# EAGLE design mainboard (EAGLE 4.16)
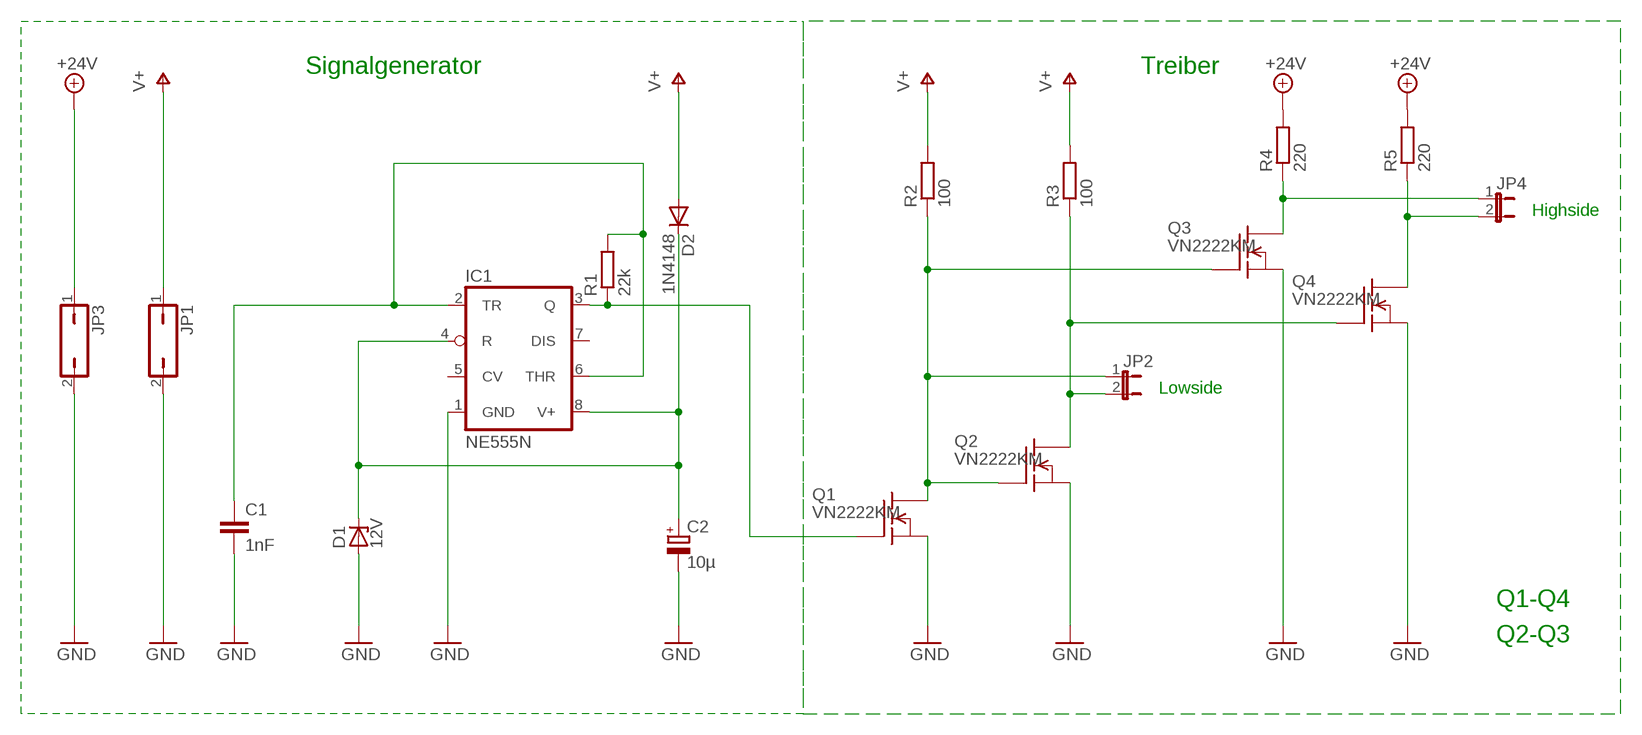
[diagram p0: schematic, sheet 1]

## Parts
C1  1nF  C-EU050-030X075  [C050-030X075]
C2  10µ  CPOL-EUE5-6  [E5-6]
D1  12V  ZENER-DIODEZD-10  [ZDIO-10]
D2  1N4148  [DO35-10]
IC1  NE555N  [DIL08]
JP1  JP1Q  [JP1]
JP2  JP1E  [JP1]
JP3  JP1Q  [JP1]
JP4  JP1E  [JP1]
Q1  VN2222KM  [TO237]
Q2  VN2222KM  [TO237]
Q3  VN2222KM  [TO237]
Q4  VN2222KM  [TO237]
R1  22k  R-EU_0207/10  [0207/10]
R2  100  R-EU_0207/10  [0207/10]
R3  100  R-EU_0207/10  [0207/10]
R4  220  R-EU_0207/10  [0207/10]
R5  220  R-EU_0207/10  [0207/10]

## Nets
+24V: JP3.1 R4.2 R5.2
GND: C1.2 C2.- D1.A IC1.1(GND) JP1.2 JP3.2 Q1.3(S) Q2.3(S) Q3.3(S) Q4.3(S)
N$1: C1.1 IC1.2(TR) IC1.6(THR) R1.2
N$2: IC1.3(Q) Q1.2(G) R1.1
N$3: C2.+ D1.C D2.C IC1.4(R) IC1.8(V+)
N$4: JP2.1 Q1.1(D) Q2.2(G) Q3.2(G) R2.1
N$5: JP2.2 Q2.1(D) Q4.2(G) R3.1
N$6: JP4.1 Q3.1(D) R4.1
N$7: JP4.2 Q4.1(D) R5.1
V+: D2.A JP1.1 R2.2 R3.2
Unconnected: IC1.5(CV) IC1.7(DIS)

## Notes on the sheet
- Signalgenerator | Treiber
- Highside
- Lowside
- Q1-Q4
- Q2-Q3

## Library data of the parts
C1 = rcl:C-EU: CAPACITOR, European symbol
C2 = rcl:CPOL-EU: POLARIZED CAPACITOR, European symbol
D1 = diode:ZENER-DIODE: Z-Diode
D2 = diode:1N4148: DIODE
IC1 = linear:*555: TIMER
JP1 JP3 = jumper:JP1Q: JUMPER
JP2 JP4 = jumper:JP1E: JUMPER
Q1-Q4 = transistor-fet:VN2222KM: N-Channel Enhancement MOSFET (VMOS); 60V; 0,5A; 7,5Ohm
R1-R5 = rcl:R-EU_: RESISTOR, European symbol

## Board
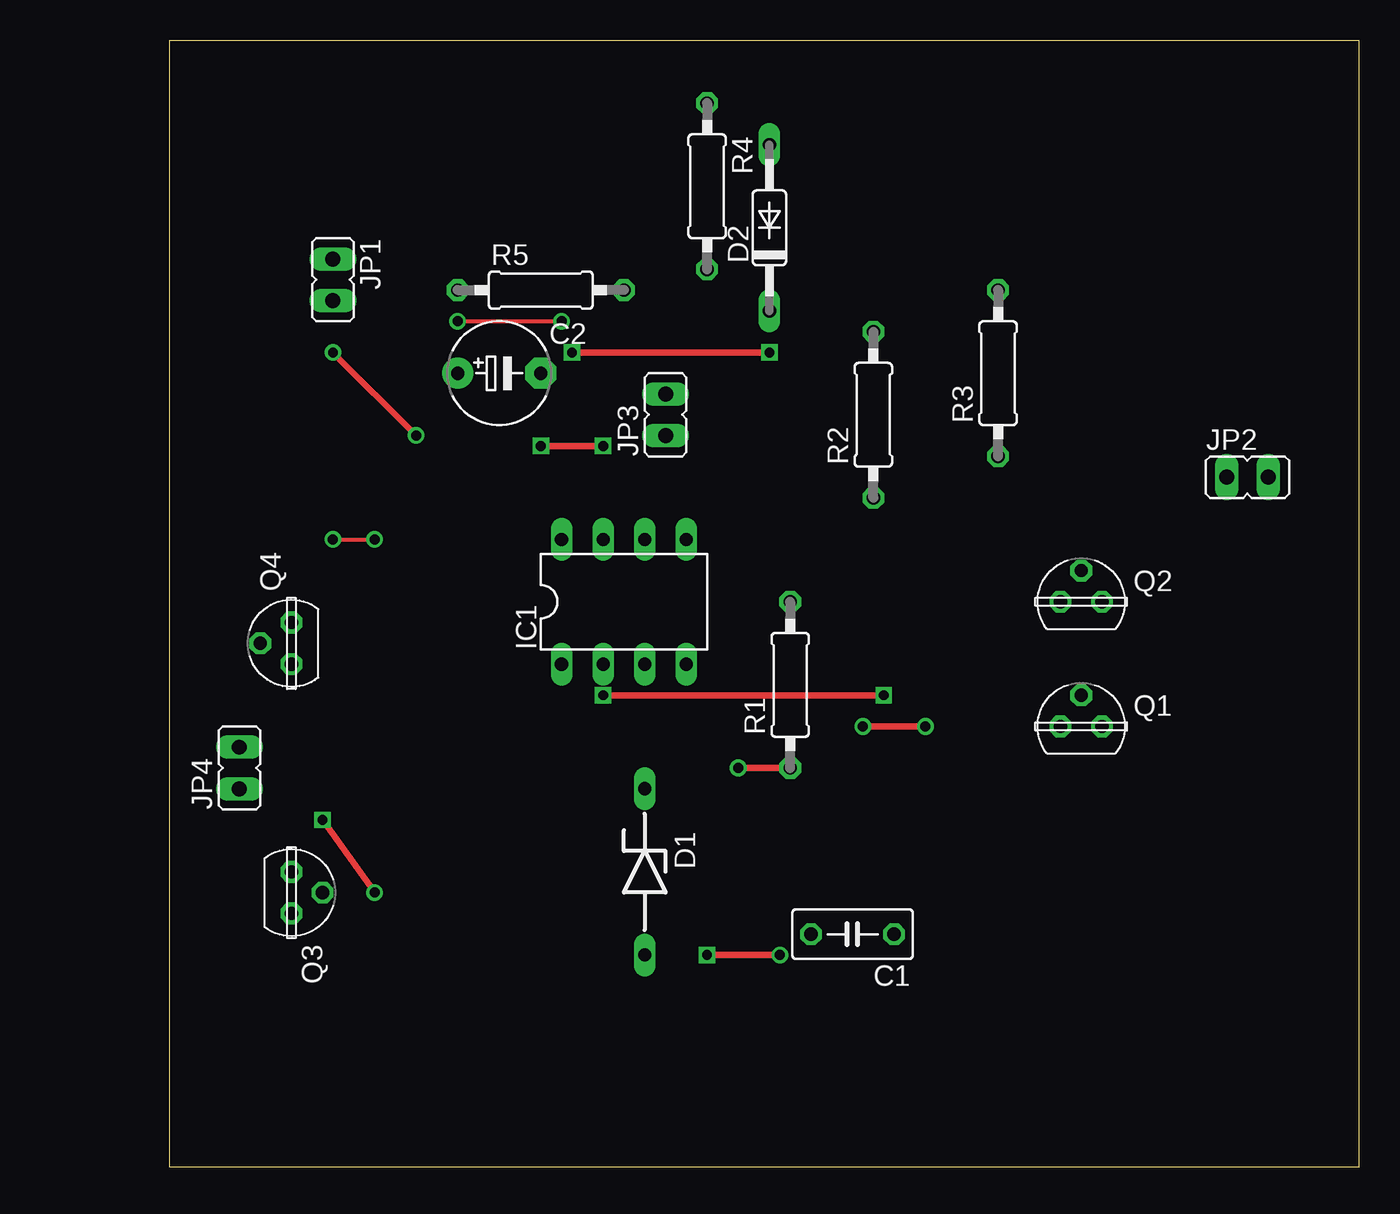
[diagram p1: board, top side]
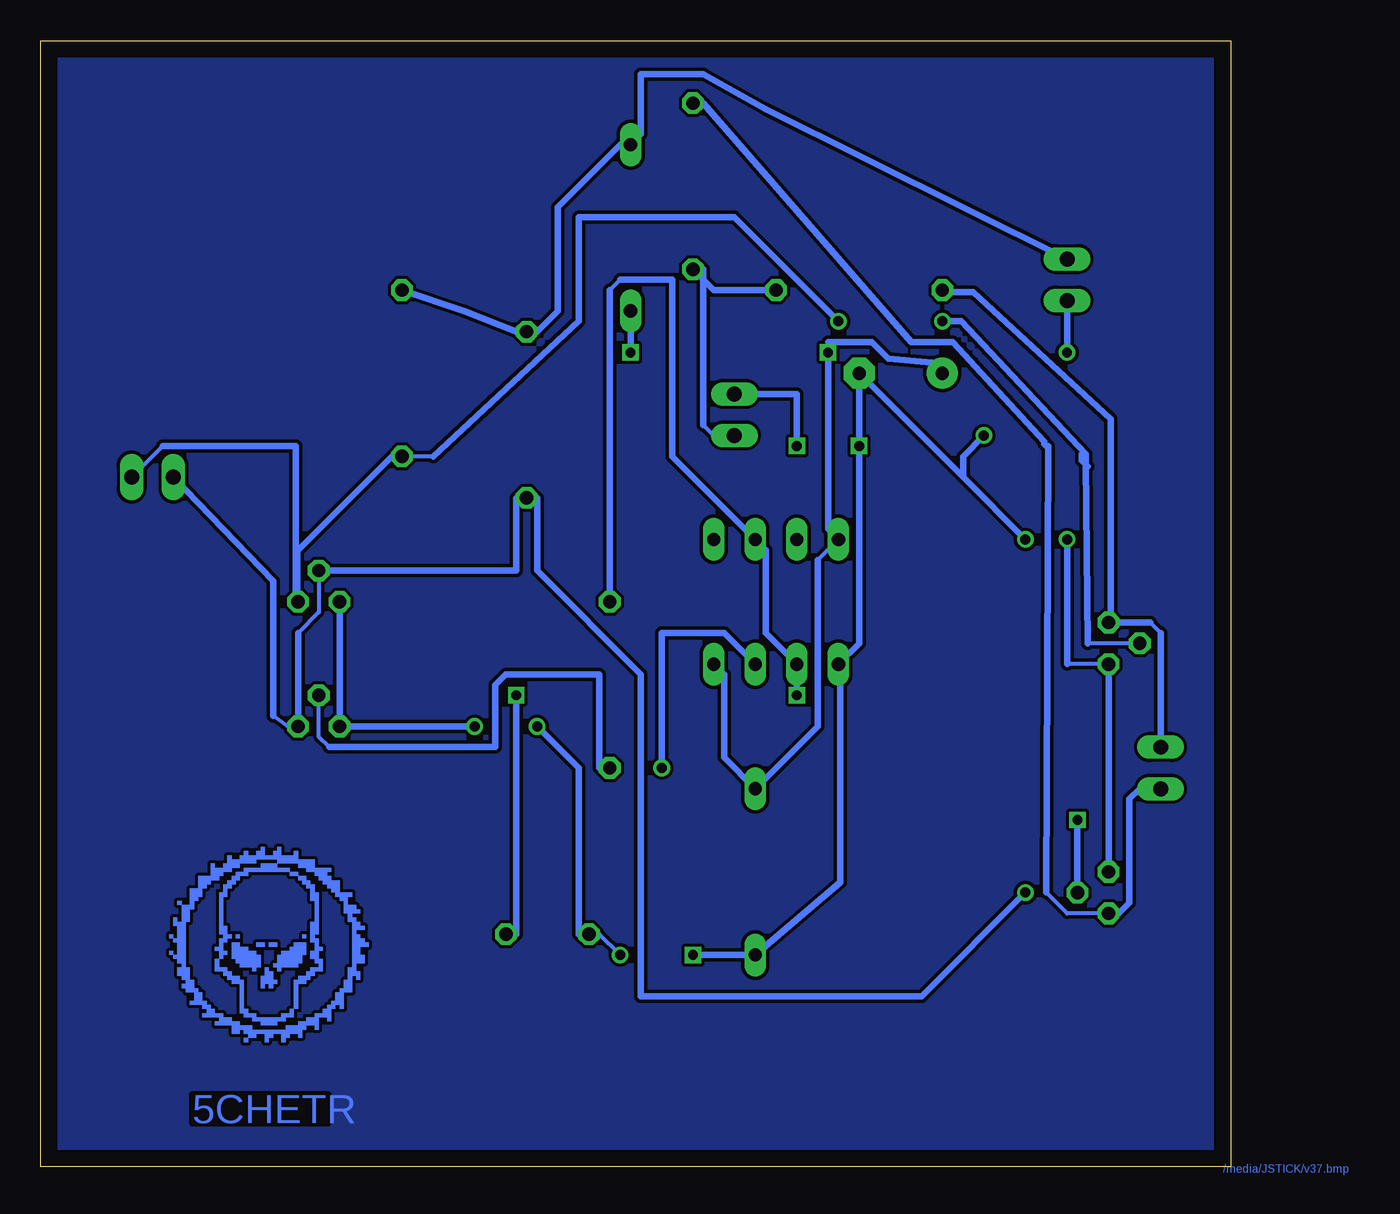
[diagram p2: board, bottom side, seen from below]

Size 72.69 x 68.82 mm. Coordinates in mm from the lower left corner, seen from the top.
Outline: 0,0 72.69,0 72.69,68.82 0,68.82 0,0
Copper layers (1*16): Top 0.035mm / dielectric 1.5mm / Bottom 0.035mm
Design rules "default": minimum track width 10mil, minimum drill 24mil, track to track 8mil, track to pad 8mil, pad to pad 8mil, via to via 8mil, smd to smd 8mil, copper to edge 40mil, drill to drill 8mil, minimum pad ring 10mil, minimum via ring 8mil, stop-mask expansion 4mil, vias tented up to drill 0mil, thermal gap 10mil

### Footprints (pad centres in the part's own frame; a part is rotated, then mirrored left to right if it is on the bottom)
C050-030X075 = drill 0.813 octagon: 1 -2.54,0; 2 2.54,0
E5-6 = drill 0.813 pad 1.905 round: + -2.54,0 | drill 0.813 pad 1.905 octagon: - 2.54,0
ZDIO-10 = drill 0.813 long: A 5.08,0; C -5.08,0
DO35-10 = drill 0.813 long: A 5.08,0; C -5.08,0
DIL08 = drill 0.813 long: 1 -3.81,-3.81; 2 -1.27,-3.81; 3 1.27,-3.81; 4 3.81,-3.81; 5 3.81,3.81; 6 1.27,3.81; 7 -1.27,3.81; 8 -3.81,3.81
JP1 = drill 0.914 long: 1 0,-1.27; 2 0,1.27
TO237 = drill 0.813 octagon: 1 1.27,0; 2 0,1.905; 3 -1.27,0
0207/10 = drill 0.813 octagon: 1 -5.08,0; 2 5.08,0

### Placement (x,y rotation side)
C1  41.74,14.22 180 top
C2  20.15,48.51 0 top
D1  29.04,18.03 270 top
D2  36.66,57.4 90 top
IC1  27.77,34.54 0 top
JP1  10,54.22 180 top
JP2  65.88,42.16 270 top
JP3  30.31,45.97 0 top
JP4  4.28,24.38 0 top
Q1  55.71,26.92 0 top
Q2  55.71,34.54 0 top
Q3  7.46,16.76 270 top
Q4  7.46,32 90 top
R1  37.94,29.46 90 top
R2  43.02,45.97 90 top
R3  50.63,48.51 90 top
R4  32.85,59.94 270 top
R5  22.7,53.59 0 top

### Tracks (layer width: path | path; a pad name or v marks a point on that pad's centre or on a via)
+24V
  Bottom 0.254: 32.22,45.33 31.58,44.7 JP3.1 | 32.22,54.86 R4.2
  Bottom 0.406: 32.22,45.33 32.22,54.86 | R5.2 31.58,53.59 R4.2
GND  (via drill 0.6, 0.61)
  Top 0.254: v10,38.35 v12.54,38.35
  Top 0.406: v42.38,26.92 v46.19,26.92 | v22.7,44.06 v26.5,44.06 | v32.85,12.95 v37.3,12.95 | v15.08,44.7 v10,49.78
  Bottom 0.254: IC1.1 23.84,30.09 | v37.3,12.95 38.57,14.22 C1.2 39.84,14.22 | Q4.3 10,30.73
  Bottom 0.406: Q2.3 Q1.3 v46.19,26.92 | 23.84,30.09 23.84,17.39 D1.A v32.85,12.95 | v42.38,26.92 39.84,24.38 39.84,14.22 | JP3.2 26.5,47.24 v26.5,44.06 | IC1.1 22.7,32 v22.7,44.06 C2.- 16.34,42.16 | 10,30.73 v10,38.35 | v12.54,38.35 16.34,42.16 | v10,49.78 JP1.2 | v15.08,44.7 16.34,43.43 16.34,42.16 | Q3.3 Q4.3
N$1  (via drill 0.6)
  Top 0.406: v26.5,28.82 v43.65,28.82
  Bottom 0.254: 28.41,37.71 IC1.6 | 37.3,54.22 37.94,53.59
  Bottom 0.406: 28.41,37.71 28.41,32.63 IC1.2 v26.5,28.82 | 37.3,54.22 34.12,54.22 34.12,43.43 IC1.6 | 37.94,53.59 R1.2 | C1.1 43.65,14.22 v43.65,28.82
N$2  (via drill 0.61)
  Top 0.406: v34.76,24.38 R1.1
  Bottom 0.254: 55.08,25.65 55.71,26.28 Q1.2 | R1.1 38.57,24.38
  Bottom 0.406: IC1.3 30.95,32.63 34.76,32.63 v34.76,24.38 | 55.08,25.65 44.92,25.65 44.92,29.46 44.28,30.09 38.57,30.09 38.57,24.38
N$3  (via drill 0.6)
  Top 0.406: v24.6,49.78 v36.66,49.78
  Bottom 0.254: 30.95,30.09 IC1.4 | 25.23,37.08 IC1.8 24.6,38.98 | v24.6,49.78 24.6,50.41
  Bottom 0.406: 30.95,30.09 30.95,25.01 D1.C 25.23,26.92 25.23,37.08 | 24.6,50.41 21.93,50.41 20.92,49.4 18.25,49.14 C2.+ | v36.66,49.78 D2.C | 24.6,38.98 v24.6,49.78
N$4  (via drill 0.6, 0.61)
  Top 0.406: v9.36,21.2 v12.54,16.76
  Bottom 0.254: 56.98,32.63 55.71,33.9 Q2.2 | 58.51,27.55 57.62,26.92 Q1.1 | 42.38,40.89 R2.1 43.65,40.89
  Bottom 0.406: 56.98,32.63 Q1.1 | 58.51,27.55 58.51,35.81 JP2.1 | v12.54,16.76 18.88,10.41 36.03,10.41 36.03,30.09 42.38,36.44 42.38,40.89 | 43.65,40.89 43.65,36.44 Q2.2 | Q3.2 v9.36,21.2
N$5  (via drill 0.61)
  Top 0.254: 17.49,51.68 v17.61,51.68 v23.96,51.68
  Bottom 0.254: Q4.2 8.73,32 | 48.73,43.43 R3.1 | 56.98,37.71 Q2.1 57.11,34.54 | 65.24,44.06 JP2.2
  Bottom 0.406: 8.73,32 8.85,43.05 | 8.85,43.05 8.85,43.3 9.11,43.56 9.11,43.17 8.85,42.92 | 8.73,42.79 8.85,42.92 | 8.85,42.92 8.85,43.05 | 8.85,43.05 8.85,43.56 16.47,51.68 v17.61,51.68 | v23.96,51.68 30.31,58.03 39.84,58.03 39.84,51.68 48.73,43.43 | 56.98,37.71 51.27,43.43 R3.1 | 65.24,44.06 57.11,44.06 57.11,34.54
N$6
  Bottom 0.254: 11.27,16.76 10,15.49 Q3.1 6.82,15.49 | 32.22,65.02 R4.1
  Bottom 0.406: 32.22,65.02 19.52,50.41 16.98,50.41 11.39,44.32 11.39,44.19 11.27,44.06 11.14,44.06 11.27,16.76 | 6.82,15.49 6.18,16.12 6.18,22.47 5.55,23.11 JP4.1
N$7
  Bottom 0.254: 4.28,32.63 4.92,33.27
  Bottom 0.406: 7.33,33.27 7.33,45.72 15.71,53.46 17.49,53.46 R5.1 | JP4.2 4.28,32.63 | 4.92,33.27 7.33,33.27 | 7.33,33.27 Q4.1
N$10
  pour Bottom: -0.04,68.96 -0.04,0.12 72.61,0.12 72.61,68.96 -0.29,68.96 -0.29,66.67
V+
  Bottom 0.254: 42.38,51.05 R2.2 43.65,51.05 | 37.3,62.48 D2.A 36.03,63.11
  Bottom 0.406: 42.38,51.05 41.11,52.32 41.11,58.67 37.3,62.48 | 43.65,51.05 46.82,52.32 R3.2 | 36.03,63.11 36.03,66.8 32.22,66.8 28.41,64.64 JP1.1
(copper drawn outside any net)
  shapes: Bottom area x206

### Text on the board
Bottom: 5CHETR | /media/JSTICK/v37.bmp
